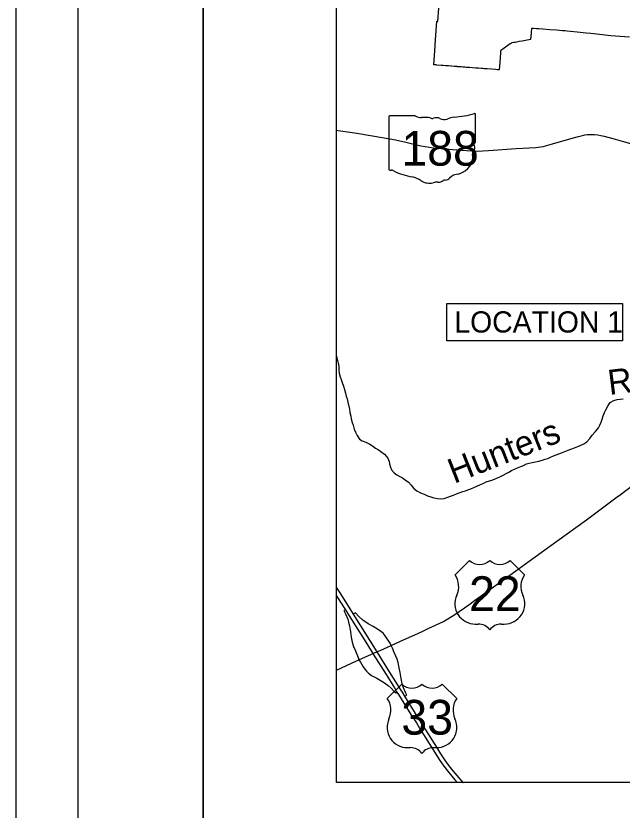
# Model space of a CAD drawing. Extents: x 0 to 34, y 0 to 22.
# Drawn here: x 0 to 4.86, y 8.77 to 15.13 of the extents above; entities that cross this region are included whole.
import ezdxf

# ---------------------------------------------------------------- set-up
doc = ezdxf.new("R2010")
doc.units = 0
for name, color, linetype in [('BR_P_Gen_Text', 7, 'Continuous'), ('GM_X_Corporation', 7, 'Continuous'), ('GM_X_Interchange_Ramps', 7, 'Continuous'), ('GM_X_Minor_River', 7, 'Continuous'), ('GM_X_Minor_River_Text', 7, 'Continuous'), ('GM_X_State_Route', 7, 'Continuous'), ('GM_X_State_Shield', 7, 'Continuous'), ('GM_X_US_Route', 7, 'Continuous'), ('GM_X_US_Shield', 7, 'Continuous'), ('SH_Border', 7, 'Continuous'), ('SH_Cut_Line', 7, 'Continuous'), ('SH_Text', 7, 'Continuous')]:
    doc.layers.add(name, color=color, linetype=linetype)

msp = doc.modelspace()

# ---------------------------------------------------------------- linework, layer by layer
at = {"layer": 'BR_P_Gen_Text'}
msp.add_lwpolyline([(3.4525, 12.8303), (4.8613, 12.8303), (4.8613, 12.53), (3.4525, 12.53)], close=True, dxfattribs=at)
at = {"layer": 'GM_X_Corporation'}
msp.add_lwpolyline([(4.9172, 14.9647), (4.7663, 14.9757), (4.7452, 14.978), (4.6059, 14.9918), (4.5697, 14.9954), (4.4964, 15.0032), (4.4178, 15.0116), (4.4011, 15.0134), (4.3922, 15.0141), (4.3812, 15.0149), (4.3322, 15.0186), (4.279, 15.0226), (4.2218, 15.0269), (4.189, 15.0294), (4.1706, 15.0308), (4.1477, 15.0325), (4.1303, 15.0338), (4.1279, 14.9999), (4.1278, 14.9992), (4.1257, 14.9701), (4.1239, 14.9446), (4.0573, 14.9325), (4.033, 14.9281), (4.0008, 14.9223), (3.9893, 14.9202), (3.9724, 14.9171), (3.9702, 14.9167), (3.9605, 14.9099), (3.9429, 14.8974), (3.9133, 14.8764), (3.8838, 14.8554), (3.8838, 14.8554), (3.8835, 14.8521), (3.8818, 14.8282), (3.8806, 14.8122), (3.8796, 14.7983), (3.8775, 14.7696), (3.8741, 14.7231), (3.8732, 14.7114), (3.8724, 14.7017), (3.8553, 14.703), (3.846, 14.7037), (3.7751, 14.7091), (3.7511, 14.7109), (3.7404, 14.7117), (3.7297, 14.7125), (3.7058, 14.7143), (3.6819, 14.7161), (3.658, 14.7179), (3.6341, 14.7197), (3.6102, 14.7215), (3.6085, 14.7216), (3.6077, 14.7216), (3.5979, 14.7224), (3.5863, 14.7234), (3.5803, 14.7239), (3.5679, 14.7249), (3.565, 14.7251), (3.5624, 14.7253), (3.5464, 14.7266), (3.5385, 14.7272), (3.5385, 14.7272), (3.5347, 14.7275), (3.5281, 14.7281), (3.5153, 14.7291), (3.5146, 14.7292), (3.5119, 14.7294), (3.4907, 14.7311), (3.4883, 14.7313), (3.4851, 14.7315), (3.4668, 14.733), (3.4485, 14.7345), (3.4429, 14.735), (3.4239, 14.7365), (3.419, 14.7369), (3.4172, 14.737), (3.4086, 14.7377), (3.3727, 14.7406), (3.3688, 14.7409), (3.3608, 14.7416), (3.3575, 14.7418), (3.3548, 14.742), (3.3514, 14.7423), (3.3488, 14.7425), (3.3597, 14.8956), (3.3603, 14.903), (3.3736, 15.0909), (3.3802, 15.0904), (3.4042, 15.4126)], dxfattribs=at)
at = {"layer": 'GM_X_Interchange_Ramps'}
for points in [[(2.6405, 10.3761), (2.6287, 10.37), (2.6411, 10.3442), (2.6587, 10.2997), (2.6658, 10.2774), (2.6733, 10.2455), (2.6811, 10.1977), (2.6861, 10.155), (2.6932, 10.1164), (2.7046, 10.0825), (2.7205, 10.0457), (2.7423, 9.9943), (2.7491, 9.9753)], [(3.0082, 10.0899), (2.9984, 10.1084), (2.9599, 10.1672), (2.9418, 10.1875), (2.9248, 10.2013), (2.8967, 10.2205), (2.8621, 10.2409), (2.8225, 10.2634), (2.7796, 10.292), (2.7472, 10.3211), (2.7203, 10.3508), (2.7018, 10.3404)], [(3.1141, 9.6832), (3.1322, 9.6924), (3.1257, 9.7076), (3.107, 9.7498), (3.0959, 9.7826), (3.0871, 9.8241), (3.0789, 9.8727), (3.0713, 9.9096), (3.0631, 9.9529), (3.0555, 9.9787), (3.0438, 10.005), (3.0309, 10.0331), (3.018, 10.0677), (3.0082, 10.0899)], [(2.7491, 9.9753), (2.7604, 9.9547), (2.7839, 9.919), (2.7967, 9.8985), (2.8096, 9.8827), (2.8246, 9.8682), (2.8506, 9.8493), (2.8921, 9.8265), (2.946, 9.7954), (2.9829, 9.7697), (3.0075, 9.7475), (3.0321, 9.7205), (3.0438, 9.7094), (3.0537, 9.7161)]]:
    msp.add_lwpolyline(points, dxfattribs=at)
at = {"layer": 'GM_X_Minor_River'}
for points in [[(2.5702, 12.4067), (2.5727, 12.3956), (2.5781, 12.3723), (2.5827, 12.3514), (2.5864, 12.3242), (2.5869, 12.2977), (2.5899, 12.2713), (2.5992, 12.2431), (2.6077, 12.2206), (2.6155, 12.1965), (2.6248, 12.1684), (2.6325, 12.1418), (2.6402, 12.1113), (2.6471, 12.088), (2.6541, 12.0663), (2.6602, 12.0398), (2.6724, 11.982), (2.677, 11.9563), (2.6831, 11.9266), (2.6876, 11.9049), (2.6953, 11.876), (2.7015, 11.8543), (2.7108, 11.8238), (2.7201, 11.7989), (2.7342, 11.7707), (2.7531, 11.7425), (2.7737, 11.7279), (2.8032, 11.7196), (2.8349, 11.7016), (2.8563, 11.6894), (2.8817, 11.6716), (2.9047, 11.6577), (2.9253, 11.6439), (2.9523, 11.6236), (2.9791, 11.5905), (2.9908, 11.5648), (2.9938, 11.5447), (3.0007, 11.5182), (3.0109, 11.4957), (3.0322, 11.473), (3.0528, 11.4576), (3.0774, 11.4438), (3.098, 11.4316), (3.1202, 11.4169), (3.1456, 11.3991), (3.1677, 11.3748), (3.189, 11.3474), (3.2135, 11.3295), (3.2429, 11.3132), (3.2707, 11.3017), (3.2977, 11.2895), (3.3256, 11.2796), (3.3479, 11.273), (3.3773, 11.2671), (3.3997, 11.2645), (3.4324, 11.2682), (3.4612, 11.2775), (3.4821, 11.2854), (3.5069, 11.294), (3.5293, 11.305), (3.5526, 11.3128), (3.5806, 11.3229), (3.6022, 11.3291), (3.6222, 11.337), (3.6454, 11.3456)], [(3.6454, 11.3456), (3.6695, 11.3542), (3.6943, 11.3651), (3.724, 11.3793), (3.7488, 11.3911), (3.7689, 11.3997), (3.8145, 11.4145), (3.8353, 11.4215), (3.8578, 11.4317), (3.8818, 11.4427), (3.9051, 11.4545), (3.9283, 11.4672), (3.9492, 11.4782), (3.9717, 11.4908), (3.9941, 11.5026), (4.019, 11.5136), (4.0454, 11.5238), (4.0678, 11.5316), (4.0927, 11.5442), (4.1135, 11.5512), (4.1359, 11.5558), (4.1623, 11.5612), (4.1911, 11.5673), (4.2167, 11.5735), (4.2399, 11.5821), (4.2623, 11.5883), (4.2824, 11.5977), (4.308, 11.6079), (4.3288, 11.6165), (4.3513, 11.6259), (4.3713, 11.6337), (4.3985, 11.6439), (4.4242, 11.6533), (4.4474, 11.6627), (4.4754, 11.6744), (4.5019, 11.6838), (4.5227, 11.6916), (4.55, 11.705), (4.5757, 11.7224), (4.5983, 11.7486), (4.6185, 11.7741), (4.6443, 11.8027), (4.6677, 11.8345), (4.6783, 11.8553), (4.6897, 11.88), (4.6979, 11.904), (4.7062, 11.9295), (4.7168, 11.9551), (4.7282, 11.9782), (4.7453, 12.0117), (4.7631, 12.0356), (4.7911, 12.0514), (4.8184, 12.0599), (4.8431, 12.0629), (4.8655, 12.0651)]]:
    msp.add_lwpolyline(points, dxfattribs=at)
at = {"layer": 'GM_X_State_Route'}
msp.add_lwpolyline([(2.5702, 14.2193), (2.5827, 14.2172), (2.7309, 14.194), (2.9502, 14.1572), (3.0405, 14.1415), (3.1237, 14.1234), (3.2447, 14.0943), (3.3136, 14.081), (3.3481, 14.0765), (3.4069, 14.0706), (3.4983, 14.0629), (3.6094, 14.055), (3.7012, 14.0515), (3.7406, 14.0523), (3.7882, 14.0563), (4.0086, 14.0704), (4.1655, 14.0806), (4.2241, 14.0888), (4.3004, 14.1082), (4.4573, 14.1549), (4.5077, 14.1691), (4.5394, 14.177), (4.5586, 14.1808), (4.5779, 14.1836), (4.5973, 14.1849), (4.6167, 14.1848), (4.6362, 14.1836), (4.6622, 14.1807), (4.6879, 14.1764), (4.7133, 14.1707), (4.783, 14.1513), (4.8569, 14.1299), (5.0476, 14.0772)], dxfattribs=at)
at = {"layer": 'GM_X_State_Shield'}
for p, q in [((2.9887, 14.3267), (2.9887, 13.9045)), ((3.1991, 14.3339), (2.9955, 14.3339)), ((3.6839, 14.1236), (3.6839, 14.3444)), ((3.6838, 14.1236), (3.6839, 14.1236))]:
    msp.add_line(p, q, dxfattribs=at)
for centre, major_axis, start_param, end_param in [((2.9967, 14.3276), (0.00805, 0), 1.712693, 3.28349), ((3.2476, 14.3829), (0.0781, 0), 4.042523, 4.731795), ((3.2735, 14.0969), (0.2804, 0), 1.404758, 1.657858), ((3.3703, 14.281), (0.0469, 0), 0.950623, 2.079405), ((3.5303, 14.205), (0.1483, 0), 1.699011, 2.107814), ((3.4363, 14.9094), (0.7373, 0), 4.814394, 5.042369), ((3.6762, 14.3453), (0.00774, 0), 6.141152, 7.989035), ((3.3372, 14.3297), (0.0225, 0), 3.836095, 5.185415), ((3.4308, 14.3479), (0.0564, 0), 4.081561, 5.145723), ((3.6821, 14.1074), (0.012, 0), 1.883978, 3.671073), ((3.6059, 14.0794), (0.0719, 0), 5.934695, 6.695948), ((3.6757, 14.1227), (0.00828, 0), 5.05454, 6.418171), ((3.4776, 14.0031), (0.1844, 0), 5.101752, 6.440018), ((3.7116, 14.0312), (0.0523, 0), 2.387724, 3.262537), ((2.9967, 13.9036), (0.00813, 0), 3.00124, 4.508301), ((2.998, 13.9468), (0.062, 0), 4.665946, 4.897461), ((3.0106, 13.8802), (0.0224, 0), 0.519207, 1.627899), ((3.2929, 14.2594), (0.5324, 0), 4.195997, 4.488961), ((3.1342, 13.7149), (0.1666, 0), 0.823519, 1.323587), ((3.3144, 13.8781), (0.1057, 0), 4.026481, 4.996735), ((3.3832, 13.8465), (0.0563, 0), 4.691044, 5.507374), ((3.4341, 13.8056), (0.0159, 0), 1.147584, 2.315152), ((3.4274, 13.8636), (0.0596, 0), 4.937069, 5.64225), ((3.5553, 13.786), (0.101, 0), 1.647645, 2.488434), ((3.3755, 13.7321), (0.0869, 0), 1.495662, 1.94098)]:
    msp.add_ellipse(centre, major_axis=major_axis, ratio=0.8, start_param=start_param, end_param=end_param, dxfattribs=at)
at = {"layer": 'GM_X_US_Route'}
for p, q in [((2.7491, 9.9753), (2.8496, 10.0195)), ((2.5702, 9.8924), (2.6887, 9.9474)), ((2.6887, 9.9474), (2.7491, 9.9753))]:
    msp.add_line(p, q, dxfattribs=at)
for points in [[(4.8306, 11.2894), (4.9757, 11.3977), (5.049, 11.453), (5.0966, 11.4884), (5.1596, 11.5348), (5.1916, 11.559), (5.2071, 11.5707)], [(3.7393, 10.4957), (3.7497, 10.5029), (4.0252, 10.7004), (4.1135, 10.7657), (4.3354, 10.9251), (4.5717, 11.0962), (4.7754, 11.2477), (4.8289, 11.2881), (4.8306, 11.2894)], [(2.5702, 10.5512), (2.5998, 10.5043), (2.7018, 10.3404), (2.8924, 10.0385), (2.991, 9.8793), (3.0556, 9.7762), (3.0822, 9.7332), (3.0943, 9.7143), (3.1141, 9.6832), (3.2134, 9.5234), (3.2828, 9.4129), (3.37, 9.2734), (3.4034, 9.2211), (3.4347, 9.1728), (3.4696, 9.1242), (3.5003, 9.0853), (3.5331, 9.0463), (3.5814, 8.9918), (3.583, 8.9902)], [(2.5702, 10.4874), (2.5961, 10.4458), (2.6405, 10.3761)], [(3.3045, 10.2244), (3.4253, 10.2813), (3.5178, 10.337), (3.63, 10.416), (3.6738, 10.4505), (3.7013, 10.4693), (3.7393, 10.4957)], [(2.6405, 10.3761), (2.6716, 10.3261), (2.7409, 10.2162), (2.7901, 10.1383), (2.8597, 10.0239), (2.8618, 10.0206)], [(3.0813, 10.1228), (3.246, 10.1969), (3.3045, 10.2244)], [(2.9183, 10.05), (3.0082, 10.0899), (3.0813, 10.1228)], [(2.8496, 10.0195), (2.8597, 10.0239), (2.8924, 10.0385), (2.9183, 10.05)], [(2.8618, 10.0206), (2.9665, 9.8557), (3.033, 9.7487), (3.0537, 9.7161), (3.0665, 9.6955), (3.0875, 9.662), (3.1658, 9.5358), (3.2088, 9.4683), (3.2339, 9.4272), (3.2664, 9.3752), (3.3573, 9.2313), (3.3929, 9.1759), (3.43, 9.1221), (3.4687, 9.071), (3.5176, 9.0122), (3.5377, 8.9902)]]:
    msp.add_lwpolyline(points, dxfattribs=at)
at = {"layer": 'GM_X_US_Shield'}
for p, q in [((3.635, 10.7711), (3.5191, 10.6552)), ((4.0753, 10.6552), (3.9594, 10.7711)), ((3.6813, 10.2613), (3.7045, 10.2613)), ((3.8899, 10.2613), (3.9131, 10.2613)), ((3.0917, 9.7807), (2.9758, 9.6649)), ((3.532, 9.6649), (3.4161, 9.7807)), ((3.138, 9.2709), (3.1612, 9.2709)), ((3.3466, 9.2709), (3.3698, 9.2709))]:
    msp.add_line(p, q, dxfattribs=at)
for centre, radius, start, end in [((3.7161, 10.8539), 0.1159, 225.573, 314.427), ((3.8783, 10.8539), 0.1159, 225.573, 314.427), ((3.3862, 10.5622), 0.1622, 334.54712, 35.00093), ((4.2082, 10.5622), 0.1622, 144.99907, 205.45288), ((3.6795, 10.4235), 0.1622, 154.83192, 270.63826), ((3.9149, 10.4235), 0.1622, 269.36174, 25.16808), ((3.7045, 10.1454), 0.1159, 36.8699, 90), ((3.8899, 10.1454), 0.1159, 90, 143.1301), ((3.1728, 9.8635), 0.1159, 225.573, 314.427), ((3.335, 9.8635), 0.1159, 225.573, 314.427), ((2.8429, 9.5718), 0.1622, 334.54712, 35.00093), ((3.6649, 9.5718), 0.1622, 144.99907, 205.45288), ((3.1362, 9.4331), 0.1622, 154.83192, 270.63826), ((3.3716, 9.4331), 0.1622, 269.36174, 25.16808), ((3.1612, 9.155), 0.1159, 36.8699, 90), ((3.3466, 9.155), 0.1159, 90, 143.1301)]:
    msp.add_arc(centre, radius, start, end, dxfattribs=at)
at = {"layer": 'SH_Border'}
for points in [[(0.5, 21.5), (1.5, 21.5), (1.5, 0.5), (0.5, 0.5)], [(1.5, 21.5), (33.5, 21.5), (33.5, 0.5), (1.5, 0.5)]]:
    msp.add_lwpolyline(points, close=True, dxfattribs=at)
at = {"layer": 'SH_Cut_Line'}
msp.add_lwpolyline([(0, 0), (34, 0), (34, 22), (0, 22)], close=True, dxfattribs=at)
at = {"layer": 'SH_Text'}
msp.add_lwpolyline([(2.5702, 20.5443), (15.6971, 20.5443), (15.6971, 8.9902), (2.5702, 8.9902)], close=True, dxfattribs=at)

# ---------------------------------------------------------------- texts
at = {"layer": 'BR_P_Gen_Text'}
msp.add_text('LOCATION 1', height=0.17, dxfattribs=at).set_placement((3.5133, 12.5969))
at = {"layer": 'GM_X_Minor_River_Text'}
for s, height, rotation, p in [('Run', 0.19974, 7.1583, (4.7557, 12.0966)), ('Hunters', 0.19975, 21.53361, (3.5113, 11.3838))]:
    msp.add_text(s, height=height, rotation=rotation, dxfattribs=at).set_placement(p)
at = {"layer": 'GM_X_State_Shield'}
msp.add_text('188', height=0.27809, dxfattribs=at).set_placement((3.0891, 13.9343))
at = {"layer": 'GM_X_US_Shield'}
for s, p in [('22', (3.631, 10.3656)), ('33', (3.0888, 9.3752))]:
    msp.add_text(s, height=0.27809, dxfattribs=at).set_placement(p)

doc.saveas('drawing.dxf')
